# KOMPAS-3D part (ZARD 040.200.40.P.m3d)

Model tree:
1. Булева операция:1
2. Булева операция:2
3. Булева операция:3
4. Булева операция:4
5. Булева операция:5
6. Булева операция:6
7. Булева операция:7
8. Булева операция:8
9. Булева операция:9
10. Булева операция:10
11. Булева операция:11
12. Булева операция:12
13. Булева операция:13
14. Булева операция:14
15. Булева операция:15
16. Булева операция:16
17. Булева операция:17
18. Булева операция:18
19. Булева операция:19
20. Булева операция:20
21. Булева операция:21
22. Булева операция:22

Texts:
  ООО ИК Энерпред-Ярдос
